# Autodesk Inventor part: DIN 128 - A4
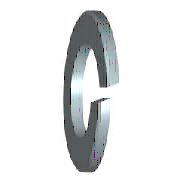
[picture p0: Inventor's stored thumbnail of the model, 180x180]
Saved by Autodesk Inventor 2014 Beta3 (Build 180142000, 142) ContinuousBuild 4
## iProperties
Created: 2010-11
Part Number: DIN 128 - A4
Material: Steel, Mild
Description: Spring Washer
Document SubType Name: Modeling
Standard: DIN 128
Designer: Beta-8540w
Standard Revision: 1994
Standards Organization: DIN
Language: en-US
Size Designation: A4
Categories: <MemberInstance><Categories><Category DisplayName="Fasteners" InternalName="e4da775c-781d-43d5-af7c-5136215cf5a6" Mnemonic="FSTN"><Category DisplayName="Washers
Density: 1 g/cm^3
Appearance: Steel
IsCustomPart: 0
Author: Beta-8540w
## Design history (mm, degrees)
sketch "Sketch1"
  geometry: C1 r 3.8 at (0, 0); C2 r 2.2 at (0, 0); 1 further point
  constraints: 2 centre point, 2 coincident
  dimensions: "d0" = 4.4 diameter of C2 (= SD1); "d1" = 7.6 diameter of C1 (= SD2)
extrude "Body" new body sketch "Sketch1" distance "d2" = 0.8 (= SD); taper "d3" = 0 deg
sketch "Sketch2"
  geometry: L1 (0, -2.2)-(0, 2.2) reference; L2 (0.8, 3.8)-(0.8, -3.8) reference; L3 (-1.2, 0)-(7.2, 0) reference; L4 (0, -0.16)-(0.8, 0.302); L5 (0, 0.16)-(0.8, 0.622)
  constraints: 4 end point, 4 point on line, 1 parallel
  dimensions: "d4" = 0.16 distance from line of L3 L4.start (= 0.2 x SD); "d5" = 0.16 distance from line of L3 L5.start (= 0.2 x SD); "d6" = 60 deg angle of L2 L4 (= FAWI)
extrude "Cut" cut sketch "Sketch2" stored distance "d7" = 0.8 (= SD); taper "d8" = 0 deg
workaxis "Work Axis1"
workplane "Work Plane1"
body "Solid1"
fillet "Fillet" dims "d13" = 0.2 (= R)
other parameters: "SD1" = 4.4 [user parameter; used in 1 equation term], "SD2" = 7.6 [user parameter; used in 1 equation term], "SD" = 0.8 [user parameter; used in 4 equation terms], "FAWI" = 60 deg [user parameter; used in 1 equation term], "d9" = 0, "d10" = 0, "d11" = 0, "d12" = 0, "R" = 0.2 [user parameter; used in 1 equation term], "NND" = 4 [user parameter]
